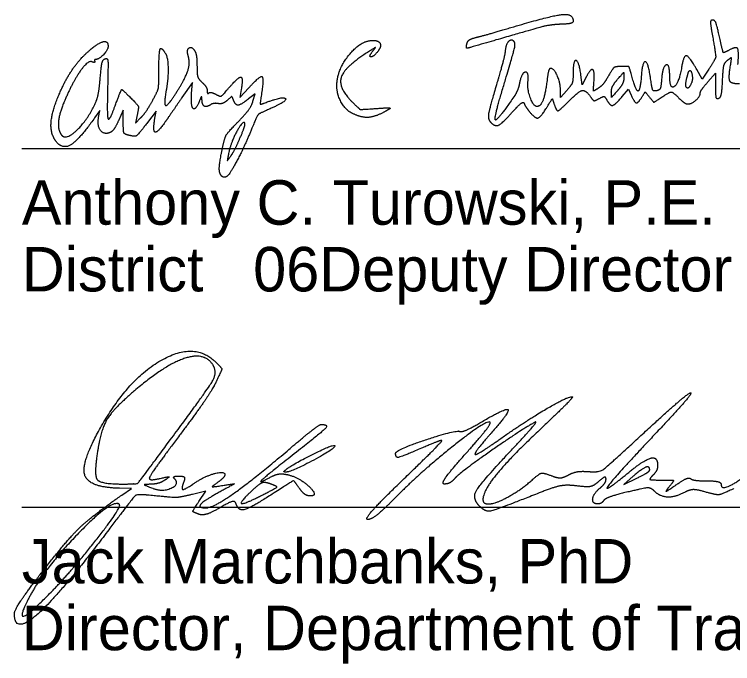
# Model space of a CAD drawing. Extents: x 0 to 34, y 0 to 22.
# Drawn here: x 24.504 to 26.766, y 3.718 to 5.762 of the extents above; entities that cross this region are included whole.
import ezdxf

# ---------------------------------------------------------------- set-up
doc = ezdxf.new("R2010")
doc.units = 0
doc.layers.add('SC_Scratch9', color=7, linetype='Continuous')
doc.layers.add('SH_Cut_Line', color=7, linetype='Continuous')

msp = doc.modelspace()

# ---------------------------------------------------------------- linework, layer by layer
at = {"layer": 'SC_Scratch9'}
for p, q in [((25.9287, 5.6679), (25.9287, 5.6679)), ((25.5689, 5.4496), (25.5689, 5.4496)), ((25.2156, 5.3738), (25.2156, 5.3738)), ((25.157, 5.2527), (25.157, 5.2527)), ((24.9902, 4.4151), (24.9902, 4.4151)), ((25.3555, 4.3253), (25.3555, 4.3253)), ((26.5045, 4.3273), (26.5045, 4.3273)), ((25.7273, 4.2962), (25.7273, 4.2962)), ((25.3107, 4.2836), (25.3107, 4.2836))]:
    msp.add_line(p, q, dxfattribs=at)
for points in [[(26.6905, 5.5886), (26.6698, 5.5574), (26.6524, 5.5884)], [(26.3033, 5.5618), (26.2923, 5.5396), (26.2879, 5.5709)], [(26.6875, 5.5488), (26.7115, 5.5761), (26.7115, 5.5352)], [(25.0623, 5.5122), (25.0648, 5.5476), (25.032, 5.4996)], [(25.2187, 5.5253), (25.2144, 5.4996), (25.2425, 5.5303)], [(26.2437, 5.522), (26.224, 5.4996), (26.2237, 5.522)], [(26.4178, 5.503), (26.4375, 5.5264), (26.4463, 5.507)], [(25.2556, 5.4879), (25.2625, 5.5119), (25.2419, 5.4957)], [(24.7697, 5.4371), (24.774, 5.4592), (24.757, 5.4354)], [(24.8473, 5.4225), (24.8471, 5.4596), (24.8322, 5.4268)], [(24.946, 5.4282), (24.9507, 5.4568), (24.9233, 5.4209)], [(24.8914, 5.4458), (24.8859, 5.4196), (24.902, 5.4356)], [(26.4527, 4.3076), (26.4232, 4.282), (26.4638, 4.3016)], [(24.8425, 4.2482), (24.8732, 4.2694), (24.8354, 4.27)], [(25.0855, 4.2283), (25.1067, 4.2607), (25.0649, 4.2506)]]:
    msp.add_lwpolyline(points, dxfattribs=at)
for points in [[(26.0677, 5.7201), (26.1931, 5.7574), (26.2635, 5.7648), (26.2635, 5.7406)], [(26.7022, 5.7436), (26.6963, 5.7436), (26.6954, 5.7325), (26.6995, 5.7096)], [(26.7309, 5.6614), (26.7165, 5.7252), (26.7101, 5.7436), (26.7022, 5.7436)], [(26.2253, 5.7304), (26.1933, 5.7295), (26.1405, 5.716), (25.9407, 5.6576)], [(26.2635, 5.7406), (26.2635, 5.7353), (26.2477, 5.7311), (26.2253, 5.7304)], [(25.9595, 5.6894), (25.9749, 5.6931), (26.0236, 5.7069), (26.0677, 5.7201)], [(26.6995, 5.7096), (26.7128, 5.6347), (26.7117, 5.6208), (26.6905, 5.5886)], [(24.7437, 5.6505), (24.7705, 5.6731), (24.7995, 5.6784), (24.7995, 5.6608)], [(25.5197, 5.5372), (25.5201, 5.5863), (25.5945, 5.6796), (25.6332, 5.6796)], [(25.6332, 5.6796), (25.6521, 5.6796), (25.6602, 5.6589), (25.6474, 5.6435)], [(25.9287, 5.6679), (25.9304, 5.677), (25.9422, 5.6851), (25.9595, 5.6894)], [(26.039, 5.5178), (26.0736, 5.6332), (26.0827, 5.671), (26.0773, 5.6764)], [(26.0773, 5.6764), (26.0685, 5.6852), (26.0512, 5.6661), (26.0495, 5.6459)], [(24.7995, 5.6608), (24.7995, 5.6502), (24.7707, 5.6196), (24.7606, 5.6196)], [(24.9595, 5.5871), (24.9595, 5.643), (24.9665, 5.6606), (24.9801, 5.6386)], [(25.0516, 5.6313), (25.0458, 5.6495), (25.0625, 5.6619), (25.0723, 5.6466)], [(25.6325, 5.6454), (25.6421, 5.6575), (25.6405, 5.6574), (25.6195, 5.6441)], [(25.9407, 5.6576), (25.9295, 5.6543), (25.9266, 5.6569), (25.9287, 5.6679)], [(26.7525, 5.6481), (26.7378, 5.6403), (26.7353, 5.6418), (26.7309, 5.6614)], [(26.7823, 5.6039), (26.7857, 5.6475), (26.7766, 5.661), (26.7525, 5.6481)], [(24.6396, 5.4959), (24.6598, 5.5471), (24.7107, 5.6228), (24.7437, 5.6505)], [(24.9801, 5.6386), (24.9876, 5.6265), (24.9892, 5.5621), (24.983, 5.5261)], [(25.015, 5.5161), (25.0431, 5.5605), (25.0586, 5.6091), (25.0516, 5.6313)], [(25.0723, 5.6466), (25.0761, 5.6405), (25.0793, 5.619), (25.0794, 5.5988)], [(25.6195, 5.6441), (25.5442, 5.5966), (25.5228, 5.531), (25.5678, 5.486)], [(25.6474, 5.6435), (25.6335, 5.6267), (25.6192, 5.6286), (25.6325, 5.6454)], [(26.0495, 5.6459), (26.0487, 5.6357), (26.0371, 5.5906), (26.0237, 5.5457)], [(26.6524, 5.5884), (26.629, 5.6303), (26.6111, 5.6328), (26.605, 5.5952)], [(24.7485, 5.6123), (24.7359, 5.6171), (24.6881, 5.5489), (24.6629, 5.4903)], [(24.7574, 5.6139), (24.7584, 5.6107), (24.7544, 5.61), (24.7485, 5.6123)], [(24.7606, 5.6196), (24.7578, 5.6196), (24.7563, 5.617), (24.7574, 5.6139)], [(24.775, 5.5629), (24.7778, 5.5982), (24.7833, 5.6196), (24.79, 5.6218)], [(24.79, 5.6218), (24.7983, 5.6245), (24.7999, 5.6055), (24.798, 5.5284)], [(26.2879, 5.5709), (26.2818, 5.6144), (26.2635, 5.6187), (26.2635, 5.5767)], [(26.5075, 5.5591), (26.5005, 5.6101), (26.4815, 5.6147), (26.4779, 5.5662)], [(26.7338, 5.5535), (26.7355, 5.5902), (26.7401, 5.6094), (26.7492, 5.6169)], [(26.7492, 5.6169), (26.7609, 5.6265), (26.7616, 5.6245), (26.7571, 5.5961)], [(24.9388, 5.4891), (24.9559, 5.5201), (24.9595, 5.5371), (24.9595, 5.5871)], [(25.0794, 5.5988), (25.0795, 5.5723), (25.084, 5.558), (25.0955, 5.5476)], [(26.1924, 5.5916), (26.1887, 5.5916), (26.1837, 5.5743), (26.1812, 5.5532)], [(26.2237, 5.522), (26.2235, 5.5464), (26.2031, 5.5916), (26.1924, 5.5916)], [(26.3291, 5.5484), (26.332, 5.5846), (26.3181, 5.5918), (26.3033, 5.5618)], [(26.4155, 5.5978), (26.3961, 5.5973), (26.3878, 5.5911), (26.3747, 5.5679)], [(26.4493, 5.5629), (26.4407, 5.5954), (26.4377, 5.5984), (26.4155, 5.5978)], [(26.5675, 5.5676), (26.5675, 5.607), (26.5449, 5.5982), (26.5419, 5.5576)], [(26.605, 5.5952), (26.5969, 5.5455), (26.5675, 5.5238), (26.5675, 5.5676)], [(26.7571, 5.5961), (26.7513, 5.56), (26.7608, 5.5436), (26.7876, 5.5436)], [(24.7618, 5.4876), (24.7666, 5.4986), (24.7725, 5.5325), (24.775, 5.5629)], [(25.1806, 5.5312), (25.2101, 5.5652), (25.225, 5.5629), (25.2187, 5.5253)], [(25.2425, 5.5303), (25.2773, 5.5685), (25.2902, 5.5631), (25.2828, 5.5136)], [(26.1212, 5.5499), (26.1245, 5.5817), (26.1015, 5.5781), (26.0949, 5.5458)], [(26.2635, 5.5767), (26.2635, 5.5538), (26.2578, 5.5379), (26.2437, 5.522)], [(26.3747, 5.5679), (26.3657, 5.5518), (26.3512, 5.5342), (26.3425, 5.5288)], [(26.4032, 5.5571), (26.4221, 5.5786), (26.423, 5.5788), (26.4232, 5.562)], [(26.4779, 5.5662), (26.4746, 5.5211), (26.461, 5.5195), (26.4493, 5.5629)], [(26.6205, 5.5576), (26.6234, 5.5697), (26.6269, 5.581), (26.6284, 5.5827)], [(26.6284, 5.5827), (26.634, 5.5892), (26.641, 5.5591), (26.6366, 5.5476)], [(25.0955, 5.5476), (25.1043, 5.5396), (25.1115, 5.5276), (25.1115, 5.521)], [(26.0237, 5.5457), (25.9997, 5.4647), (25.9946, 5.4311), (26.0048, 5.4209)], [(26.0949, 5.5458), (26.092, 5.5316), (26.0839, 5.5118), (26.0769, 5.5018)], [(26.1498, 5.4716), (26.1386, 5.4716), (26.1187, 5.526), (26.1212, 5.5499)], [(26.1812, 5.5532), (26.1762, 5.5111), (26.161, 5.4716), (26.1498, 5.4716)], [(26.3425, 5.5288), (26.3277, 5.5196), (26.3269, 5.5209), (26.3291, 5.5484)], [(26.3837, 5.5171), (26.3836, 5.5268), (26.3924, 5.5448), (26.4032, 5.5571)], [(26.4232, 5.562), (26.4234, 5.5524), (26.4146, 5.5344), (26.4037, 5.522)], [(26.5263, 5.5212), (26.516, 5.5193), (26.5119, 5.5276), (26.5075, 5.5591)], [(26.5419, 5.5576), (26.5402, 5.5337), (26.5356, 5.523), (26.5263, 5.5212)], [(26.6366, 5.5476), (26.6283, 5.526), (26.6149, 5.5343), (26.6205, 5.5576)], [(26.6635, 5.5137), (26.6635, 5.518), (26.6743, 5.5338), (26.6875, 5.5488)], [(26.7215, 5.4975), (26.7278, 5.4996), (26.7324, 5.5203), (26.7338, 5.5535)], [(24.798, 5.5284), (24.7966, 5.4751), (24.7979, 5.4315), (24.8008, 5.4316)], [(24.8201, 5.4696), (24.8401, 5.5239), (24.8441, 5.526), (24.8721, 5.4974)], [(24.983, 5.5261), (24.9743, 5.4766), (24.9874, 5.4725), (25.015, 5.5161)], [(25.1115, 5.521), (25.1115, 5.5143), (25.1138, 5.5112), (25.1165, 5.514)], [(25.1382, 5.5101), (25.1526, 5.5024), (25.1582, 5.5052), (25.1806, 5.5312)], [(25.5689, 5.4496), (25.5476, 5.4598), (25.5194, 5.5101), (25.5197, 5.5372)], [(26.0769, 5.5018), (26.0249, 5.4271), (26.0132, 5.432), (26.039, 5.5178)], [(26.2518, 5.4902), (26.2818, 5.5202), (26.3025, 5.524), (26.318, 5.5023)], [(26.4037, 5.522), (26.3849, 5.5005), (26.384, 5.5003), (26.3837, 5.5171)], [(26.4808, 5.5027), (26.49, 5.5175), (26.4907, 5.5174), (26.5039, 5.5011)], [(26.5405, 5.4997), (26.5671, 5.5175), (26.5784, 5.5166), (26.5999, 5.4951)], [(26.7115, 5.5352), (26.7115, 5.506), (26.7144, 5.4952), (26.7215, 5.4975)], [(24.6342, 5.3639), (24.6185, 5.3854), (24.6211, 5.4489), (24.6396, 5.4959)], [(24.8721, 5.4974), (24.8933, 5.4758), (24.8961, 5.4683), (24.8914, 5.4458)], [(25.032, 5.4996), (25.0139, 5.4732), (24.9911, 5.44), (24.9813, 5.4259)], [(25.087, 5.4889), (25.0747, 5.4582), (25.0596, 5.4725), (25.0623, 5.5122)], [(25.095, 5.494), (25.0946, 5.5035), (25.0922, 5.502), (25.087, 5.4889)], [(25.1165, 5.514), (25.1193, 5.5167), (25.1291, 5.515), (25.1382, 5.5101)], [(25.1942, 5.4919), (25.19, 5.5029), (25.188, 5.5029), (25.1752, 5.4913)], [(25.2419, 5.4957), (25.2173, 5.4764), (25.2007, 5.4751), (25.1942, 5.4919)], [(25.2828, 5.5136), (25.2779, 5.481), (25.2788, 5.4776), (25.2911, 5.4823)], [(25.2911, 5.4823), (25.3506, 5.5052), (25.365, 5.4882), (25.3071, 5.4634)], [(26.1826, 5.4721), (26.197, 5.4956), (26.1982, 5.4962), (26.2032, 5.4804)], [(26.318, 5.5023), (26.3265, 5.4902), (26.3315, 5.4892), (26.3451, 5.4964)], [(26.3451, 5.4964), (26.3585, 5.5036), (26.3633, 5.5028), (26.3691, 5.4925)], [(26.3691, 5.4925), (26.3798, 5.4733), (26.3957, 5.4767), (26.4178, 5.503)], [(26.4463, 5.507), (26.4569, 5.4837), (26.4681, 5.4823), (26.4808, 5.5027)], [(26.5039, 5.5011), (26.5173, 5.4845), (26.5176, 5.4845), (26.5405, 5.4997)], [(26.5999, 5.4951), (26.6085, 5.4866), (26.6197, 5.4796), (26.6249, 5.4796)], [(26.6249, 5.4796), (26.6366, 5.4796), (26.6635, 5.5034), (26.6635, 5.5137)], [(24.6629, 5.4903), (24.6464, 5.4518), (24.6408, 5.4009), (24.6511, 5.3842)], [(24.6511, 5.3842), (24.6644, 5.3627), (24.7369, 5.4304), (24.7618, 5.4876)], [(24.902, 5.4356), (24.9109, 5.4444), (24.9275, 5.4685), (24.9388, 5.4891)], [(25.1215, 5.4769), (25.1084, 5.4687), (25.0956, 5.477), (25.095, 5.494)], [(25.1462, 5.4807), (25.1381, 5.4821), (25.127, 5.4803), (25.1215, 5.4769)], [(25.1752, 5.4913), (25.1673, 5.4842), (25.1542, 5.4794), (25.1462, 5.4807)], [(25.2086, 5.4232), (25.2307, 5.4456), (25.2518, 5.4747), (25.2556, 5.4879)], [(25.5678, 5.486), (25.5906, 5.4633), (25.5952, 5.4619), (25.6398, 5.4651)], [(26.0719, 5.4536), (26.0918, 5.4759), (26.1072, 5.4875), (26.1092, 5.4817)], [(26.1092, 5.4817), (26.1112, 5.4762), (26.1191, 5.4639), (26.1269, 5.4543)], [(26.1269, 5.4543), (26.1444, 5.4327), (26.1621, 5.4383), (26.1826, 5.4721)], [(26.2032, 5.4804), (26.2106, 5.4572), (26.2208, 5.4592), (26.2518, 5.4902)], [(24.8008, 5.4316), (24.8038, 5.4316), (24.8125, 5.4487), (24.8201, 5.4696)], [(25.3071, 5.4634), (25.2757, 5.4499), (25.2684, 5.4421), (25.2535, 5.4057)], [(25.6639, 5.4518), (25.6366, 5.4377), (25.5956, 5.4367), (25.5689, 5.4496)], [(25.6398, 5.4651), (25.666, 5.467), (25.6875, 5.4675), (25.6875, 5.4663)], [(25.6875, 5.4663), (25.6875, 5.465), (25.6769, 5.4585), (25.6639, 5.4518)], [(26.0048, 5.4209), (26.0182, 5.4075), (26.0408, 5.4185), (26.0719, 5.4536)], [(24.757, 5.4354), (24.7073, 5.3656), (24.6552, 5.3352), (24.6342, 5.3639)], [(24.8052, 5.3893), (24.7863, 5.3821), (24.7648, 5.4112), (24.7697, 5.4371)], [(24.8322, 5.4268), (24.8241, 5.4087), (24.8119, 5.3919), (24.8052, 5.3893)], [(24.9813, 5.4259), (24.9565, 5.3901), (24.94, 5.3912), (24.946, 5.4282)], [(24.8615, 5.3818), (24.8507, 5.3846), (24.8474, 5.394), (24.8473, 5.4225)], [(24.9233, 5.4209), (24.894, 5.3826), (24.8837, 5.376), (24.8615, 5.3818)], [(25.16, 5.3426), (25.1667, 5.3738), (25.1773, 5.3914), (25.2086, 5.4232)], [(25.2535, 5.4057), (25.2283, 5.344), (25.1799, 5.253), (25.1705, 5.2499)], [(25.2295, 5.4202), (25.2229, 5.4268), (25.1859, 5.3581), (25.1798, 5.3276)], [(25.2156, 5.3738), (25.2255, 5.397), (25.2318, 5.4179), (25.2295, 5.4202)], [(25.1858, 5.3156), (25.1922, 5.3244), (25.2056, 5.3506), (25.2156, 5.3738)], [(25.157, 5.2527), (25.149, 5.2607), (25.1502, 5.2969), (25.16, 5.3426)], [(25.1798, 5.3276), (25.1745, 5.3016), (25.175, 5.3007), (25.1858, 5.3156)], [(25.1705, 5.2499), (25.1661, 5.2484), (25.16, 5.2497), (25.157, 5.2527)], [(24.7789, 4.4659), (24.8651, 4.6162), (25.0732, 4.7323), (25.1389, 4.6666)], [(25.1299, 4.6574), (25.104, 4.6995), (24.9779, 4.6583), (24.8825, 4.5767)], [(25.1389, 4.6666), (25.1577, 4.6478), (25.1577, 4.6428), (25.1394, 4.6044)], [(24.9902, 4.4151), (25.1115, 4.5786), (25.144, 4.6348), (25.1299, 4.6574)], [(25.1394, 4.6044), (25.1284, 4.5814), (25.0767, 4.5058), (25.0245, 4.4365)], [(24.8825, 4.5767), (24.8159, 4.5196), (24.7771, 4.4555), (24.766, 4.3843)], [(26.4869, 4.4448), (26.5619, 4.5139), (26.6279, 4.5705), (26.6336, 4.5705)], [(26.6336, 4.5705), (26.6394, 4.5706), (26.5873, 4.5105), (26.518, 4.4369)], [(26.0326, 4.4243), (26.1131, 4.481), (26.2445, 4.5582), (26.2602, 4.5582)], [(26.2602, 4.5582), (26.265, 4.5582), (26.2237, 4.5156), (26.1684, 4.4635)], [(25.9736, 4.4779), (26.0524, 4.524), (26.0646, 4.5108), (26.0054, 4.4435)], [(26.0017, 4.4776), (25.9921, 4.4872), (25.7824, 4.3203), (25.7045, 4.241)], [(26.142, 4.4772), (26.0929, 4.4494), (25.9046, 4.3172), (25.8914, 4.3012)], [(25.908, 4.4486), (25.9136, 4.4468), (25.9431, 4.46), (25.9736, 4.4779)], [(25.9239, 4.3772), (25.9702, 4.429), (26.0052, 4.4741), (26.0017, 4.4776)], [(26.0768, 4.3982), (26.123, 4.4475), (26.1523, 4.483), (26.142, 4.4772)], [(24.8354, 4.27), (24.7375, 4.2717), (24.7141, 4.3529), (24.7789, 4.4659)], [(25.369, 4.3924), (25.4194, 4.4352), (25.4649, 4.4704), (25.4701, 4.4705)], [(25.4701, 4.4705), (25.495, 4.471), (25.4716, 4.4454), (25.3857, 4.3782)], [(26.1684, 4.4635), (26.0687, 4.3698), (25.9795, 4.2616), (25.9795, 4.2346)], [(25.0245, 4.4365), (24.9722, 4.3671), (24.9295, 4.3065), (24.9295, 4.3017)], [(25.7047, 4.3801), (25.7049, 4.3906), (25.8923, 4.4538), (25.908, 4.4486)], [(26.0054, 4.4435), (25.9774, 4.4116), (25.9545, 4.382), (25.9545, 4.3775)], [(26.3119, 4.3224), (26.3453, 4.3196), (26.3688, 4.336), (26.4869, 4.4448)], [(26.518, 4.4369), (26.3885, 4.2993), (26.3564, 4.2521), (26.4386, 4.3198)], [(24.844, 4.2832), (24.8907, 4.2832), (24.8953, 4.2873), (24.9902, 4.4151)], [(25.7273, 4.2962), (25.7983, 4.3647), (25.8537, 4.4207), (25.8502, 4.4207)], [(25.8502, 4.4207), (25.8468, 4.4207), (25.8178, 4.4094), (25.7857, 4.3957)], [(25.9545, 4.3775), (25.9545, 4.3731), (25.9896, 4.3941), (26.0326, 4.4243)], [(25.1076, 4.2082), (25.1307, 4.2082), (25.2567, 4.297), (25.369, 4.3924)], [(25.3555, 4.3253), (25.3759, 4.3431), (25.5079, 4.4089), (25.5131, 4.4038)], [(25.5131, 4.4038), (25.5193, 4.3976), (25.3767, 4.3207), (25.359, 4.3207)], [(25.7857, 4.3957), (25.7231, 4.3689), (25.7044, 4.3652), (25.7047, 4.3801)], [(25.9697, 4.2126), (25.9445, 4.2378), (25.9734, 4.2879), (26.0768, 4.3982)], [(26.7295, 4.2817), (26.7295, 4.2589), (26.8248, 4.3203), (26.8951, 4.3885)], [(24.766, 4.3843), (24.7545, 4.3109), (24.776, 4.2832), (24.844, 4.2832)], [(25.3857, 4.3782), (25.2925, 4.3052), (25.271, 4.2836), (25.315, 4.3071)], [(25.8581, 4.2832), (25.8478, 4.2832), (25.8767, 4.3245), (25.9239, 4.3772)], [(26.4386, 4.3198), (26.487, 4.3597), (26.5295, 4.37), (26.5295, 4.3419)], [(26.5295, 4.3419), (26.5295, 4.333), (26.5227, 4.3189), (26.5145, 4.3107)], [(25.0736, 4.2876), (25.1025, 4.3074), (25.167, 4.3249), (25.167, 4.3129)], [(25.359, 4.3207), (25.3542, 4.3207), (25.3526, 4.3227), (25.3555, 4.3253)], [(26.2489, 4.3119), (26.2623, 4.3195), (26.2906, 4.3242), (26.3119, 4.3224)], [(26.5045, 4.3273), (26.5045, 4.3407), (26.4804, 4.3316), (26.4527, 4.3076)], [(26.4638, 4.3016), (26.4862, 4.3125), (26.5045, 4.324), (26.5045, 4.3273)], [(24.9295, 4.3017), (24.9295, 4.2969), (24.9449, 4.2966), (24.9638, 4.301)], [(24.9795, 4.2963), (24.9692, 4.2893), (24.9495, 4.2831), (24.9357, 4.2826)], [(24.9399, 4.2699), (24.9698, 4.2579), (25.026, 4.2825), (25.0086, 4.2999)], [(24.9638, 4.301), (24.9894, 4.3069), (24.9934, 4.3057), (24.9795, 4.2963)], [(25.0086, 4.2999), (25.004, 4.3045), (25.0103, 4.3082), (25.0225, 4.3082)], [(25.0225, 4.3082), (25.037, 4.3082), (25.0422, 4.3018), (25.0375, 4.2894)], [(25.167, 4.3129), (25.167, 4.3084), (25.1572, 4.2976), (25.1453, 4.2889)], [(25.315, 4.3071), (25.3276, 4.3139), (25.3515, 4.316), (25.3681, 4.3118)], [(25.3681, 4.3118), (25.4042, 4.3026), (25.4625, 4.2457), (25.4358, 4.2457)], [(25.617, 4.1714), (25.6067, 4.1716), (25.6563, 4.2278), (25.7273, 4.2962)], [(25.8914, 4.3012), (25.8831, 4.2913), (25.8682, 4.2832), (25.8581, 4.2832)], [(25.9975, 4.2207), (26.0192, 4.2207), (26.1006, 4.2659), (26.137, 4.2982)], [(26.137, 4.2982), (26.1573, 4.3162), (26.1701, 4.3189), (26.1939, 4.3099)], [(26.1939, 4.3099), (26.2141, 4.3022), (26.2329, 4.3029), (26.2489, 4.3119)], [(26.367, 4.2992), (26.367, 4.3063), (26.3568, 4.3029), (26.3444, 4.2916)], [(26.3482, 4.2707), (26.3585, 4.2793), (26.367, 4.2921), (26.367, 4.2992)], [(26.5145, 4.3107), (26.5028, 4.299), (26.5087, 4.2957), (26.541, 4.2957)], [(26.5871, 4.2802), (26.6085, 4.2952), (26.6293, 4.3042), (26.6332, 4.3003)], [(26.6332, 4.3003), (26.6371, 4.2964), (26.6604, 4.2932), (26.6849, 4.2932)], [(24.9357, 4.2826), (24.9133, 4.2817), (24.9138, 4.2804), (24.9399, 4.2699)], [(25.0375, 4.2894), (25.0285, 4.2662), (25.0414, 4.2655), (25.0736, 4.2876)], [(25.1453, 4.2889), (25.1264, 4.2751), (25.1284, 4.2738), (25.161, 4.2787)], [(25.161, 4.2787), (25.1977, 4.2843), (25.1976, 4.284), (25.1522, 4.2589)], [(25.3107, 4.2836), (25.2935, 4.2899), (25.277, 4.2848), (25.2576, 4.2671)], [(25.2826, 4.2473), (25.329, 4.271), (25.3325, 4.2756), (25.3107, 4.2836)], [(25.4011, 4.2704), (25.3843, 4.2944), (25.3822, 4.294), (25.3165, 4.2516)], [(26.2749, 4.2772), (26.2457, 4.281), (26.2058, 4.2745), (26.1693, 4.2601)], [(26.3444, 4.2916), (26.3287, 4.2775), (26.3075, 4.2731), (26.2749, 4.2772)], [(26.541, 4.2957), (26.5785, 4.2957), (26.5809, 4.2936), (26.5654, 4.2743)], [(26.5654, 4.2743), (26.5533, 4.2593), (26.5598, 4.2611), (26.5871, 4.2802)], [(26.6849, 4.2932), (26.7094, 4.2932), (26.7295, 4.288), (26.7295, 4.2817)], [(25.1522, 4.2589), (25.1011, 4.2307), (25.0814, 4.2082), (25.1076, 4.2082)], [(25.3165, 4.2516), (25.2476, 4.2073), (25.2101, 4.1975), (25.202, 4.2219)], [(25.2576, 4.2671), (25.2133, 4.2266), (25.2246, 4.2177), (25.2826, 4.2473)], [(25.4358, 4.2457), (25.4262, 4.2457), (25.4106, 4.2568), (25.4011, 4.2704)], [(26.1693, 4.2601), (26.0233, 4.2024), (25.9882, 4.1941), (25.9697, 4.2126)], [(26.3412, 4.2207), (26.3229, 4.2207), (26.3274, 4.2534), (26.3482, 4.2707)], [(26.4355, 4.2582), (26.3972, 4.249), (26.3629, 4.2368), (26.3594, 4.2311)], [(26.5199, 4.2603), (26.5088, 4.2714), (26.4887, 4.2709), (26.4355, 4.2582)], [(26.6162, 4.2578), (26.5854, 4.2413), (26.5376, 4.2426), (26.5199, 4.2603)], [(26.6807, 4.2579), (26.6538, 4.2656), (26.6307, 4.2655), (26.6162, 4.2578)], [(26.7698, 4.2692), (26.7324, 4.2507), (26.7138, 4.2483), (26.6807, 4.2579)], [(24.5916, 4.006), (24.6692, 4.1064), (24.7493, 4.1837), (24.8425, 4.2482)], [(24.9237, 4.2483), (24.8903, 4.2516), (24.8786, 4.2411), (24.8019, 4.1394)], [(25.0649, 4.2506), (25.0246, 4.2408), (25.0023, 4.2405), (24.9237, 4.2483)], [(25.0843, 4.1883), (25.0661, 4.1953), (25.0662, 4.1989), (25.0855, 4.2283)], [(25.202, 4.2219), (25.1991, 4.2304), (25.1799, 4.2252), (25.1508, 4.2081)], [(25.7045, 4.241), (25.6667, 4.2025), (25.6273, 4.1712), (25.617, 4.1714)], [(25.9795, 4.2346), (25.9795, 4.227), (25.9876, 4.2207), (25.9975, 4.2207)], [(26.3594, 4.2311), (26.3559, 4.2254), (26.3477, 4.2207), (26.3412, 4.2207)], [(24.8354, 4.2189), (24.8145, 4.2398), (24.596, 4.0142), (24.5497, 3.9238)], [(24.6198, 3.9426), (24.6874, 4.0116), (24.8431, 4.2112), (24.8354, 4.2189)], [(25.1508, 4.2081), (25.1252, 4.193), (25.0953, 4.1841), (25.0843, 4.1883)], [(24.8019, 4.1394), (24.6496, 3.9374), (24.5045, 3.8087), (24.5045, 3.8757)], [(24.5045, 3.8757), (24.5045, 3.8854), (24.5437, 3.944), (24.5916, 4.006)], [(24.5497, 3.9238), (24.5184, 3.8629), (24.55, 3.8713), (24.6198, 3.9426)]]:
    msp.add_open_spline(points, degree=2, dxfattribs=at)
at = {"layer": 'SH_Cut_Line'}
for p, q in [((24.5279, 5.3395), (28.0279, 5.3395)), ((24.5279, 4.2101), (28.0279, 4.2101))]:
    msp.add_line(p, q, dxfattribs=at)

# ---------------------------------------------------------------- texts
at = {"layer": 'SC_Scratch9'}
for s, p in [('Anthony C. Turowski, P.E.', (24.5279, 5.0995)), ('District       Deputy Director', (24.5279, 4.8895)), ('              06', (24.5279, 4.8895)), ('Jack Marchbanks, PhD', (24.5279, 3.9701)), ('Director, Department of Transportation', (24.5279, 3.7601))]:
    msp.add_text(s, height=0.14, dxfattribs=at).set_placement(p)

doc.saveas('drawing.dxf')
